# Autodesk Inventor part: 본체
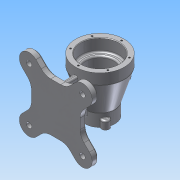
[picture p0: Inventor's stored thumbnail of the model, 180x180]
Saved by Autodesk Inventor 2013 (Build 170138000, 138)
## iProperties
Created: 2018-03
Part Number: 본체
Material: 알루미늄 6061
Document SubType Name: Modeling
Designer: Administrator
Density: 2.71 g/cm^3
Mass: 1014.04 g
Surface Area: 856.065 cm^2
Volume: 374.186 cm^3
Author: Administrator
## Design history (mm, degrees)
sketch "스케치1"
  geometry: L1 (45, 50)-(35, 50); L2 (35, 50)-(35, 27); L3 (35, 27)-(26, 27); L4 (26, 27)-(26, -20); L5 (26, -20)-(20, -20); L6 (20, -20)-(20, -50); L7 (20, -50)-(27.5, -50); L8 (27.5, -50)-(27.5, -27); L9 (27.5, -27)-(45, 30); L10 (45, 30)-(45, 50); L11 (0, 0)-(0, 61.227)
  constraints: 22 end point, 7 parallel, 1 horizontal, 1 perpendicular, 1 vertical
  dimensions: "d14" = 50 distance from line of L11.start L1; "d15" = 20 distance of L9.end L1.start; "d16" = 77 distance from line of L8.end L1; "d17" = 100 distance between parallel lines of L7 L1; "d18" = 23 distance of L1.end L2.end; "d19" = 47 distance of L3.end L4.end; "d20" = 40 diameter of L6 L11; "d21" = 55 diameter of L8 L11; "d22" = 90 diameter of L10 L11; "d23" = 70 diameter of L2 L11; "d24" = 52 diameter of L4 L11
revolve "회전1" sketch "스케치1" stored, may be unused: angle "d25" = 90 deg
node "작업 평면1"
sketch "스케치3"
  geometry: L1 (45, 45)-(-45, 45); L2 (-45, 45)-(-45, -45); L3 (-45, -45)-(45, -45); L4 (45, -45)-(45, 45); L5 (0, 0)-(65.909, 65.909); L6 (0, 0)-(114.42, 0); L7 (36.77, 62.225)-(19.544, 45); L8 (62.225, 36.77)-(45, 19.544); L9 (0, 0)-(73.646, -73.646); L10 (0, 0)-(-84.879, -84.879); L11 (0, 0)-(-79.002, 79.002); L12 (-36.77, 62.225)-(-19.544, 45); L13 (45, -19.544)-(62.225, -36.77); L14 (19.544, -45)-(36.77, -62.225); L15 (-19.544, -45)-(-36.77, -62.225); L16 (-45, -19.544)-(-62.225, -36.77); L17 (-45, 19.544)-(-62.225, 36.77); A1 r 70 centre (0, 0) between (49.497, 49.497) and (49.497, -49.497); A2 r 18 centre (49.497, 49.497) between (62.225, 36.77) and (36.77, 62.225); A3 r 18 centre (-49.497, 49.497) between (-36.77, 62.225) and (-62.225, 36.77); A4 r 18 centre (-49.497, -49.497) between (-62.225, -36.77) and (-36.77, -62.225); A5 r 18 centre (49.497, -49.497) between (36.77, -62.225) and (62.225, -36.77); 3 further points
  constraints: 34 end point, 12 point on circle, 12 point on line, 10 parallel, 8 tangent, 5 centre point, 3 perpendicular, 2 midpoint, 1 coincident, 1 horizontal, 1 horizontal alignment, 1 vertical alignment
  dimensions: "d46" = 90 distance of L1.start L1.end; "d48" = 90 distance of L3.end L1.start; "d49" = 140 diameter of A1; "d50" = 45 deg angle of L6 L5; "d52" = 18 radius of A2; "d53" = 90 deg angle of L10 L9; "d54" = 90 deg angle of L10 L11; "d58" = 18 radius of A5; "d59" = 18 radius of A3; "d60" = 18 radius of A4
extrude "돌출3" join sketch "스케치3" distance "d61" = 12; taper "d62" = 0 deg
sketch "스케치4"
  geometry: L1 (-24, -4)-(24, -4); L2 (24, -4)-(24, 4); L3 (24, 4)-(-24, 4); L4 (-24, 4)-(-24, -4); L5 (-4, -37)-(4, -37); L6 (4, -37)-(4, 37); L7 (4, 37)-(-4, 37); L8 (-4, 37)-(-4, -37); 4 further points
  constraints: 16 end point, 4 parallel, 3 midpoint, 2 horizontal, 2 perpendicular, 2 vertical alignment, 1 horizontal alignment
  dimensions: "d64" = 37 distance from line of point (0, 0) L5; "d65" = 37 distance from line of point (0, 0) L7; "d67" = 48 distance between parallel lines of L2 L4; "d68" = 8 distance between parallel lines of L6 L8; "d69" = 8 distance between parallel lines of L3 L1
extrude "돌출4" join sketch "스케치4" stored distance "d70" = 12; taper "d71" = 0 deg
feature "면 기울기1" dims angle "d72" = 5 deg
node "작업 평면2"
sketch "스케치5"
  geometry: L1 (-12.5, 12.5)-(12.5, 12.5); L2 (12.5, 12.5)-(12.5, -12.5); L3 (12.5, -12.5)-(-12.5, -12.5); L4 (-12.5, -12.5)-(-12.5, 12.5); L5 (-7.5, 7.5)-(7.5, 7.5); L6 (7.5, 7.5)-(7.5, -7.5); L7 (7.5, -7.5)-(-7.5, -7.5); L8 (-7.5, -7.5)-(-7.5, 7.5); 5 further points
  constraints: 16 end point, 4 midpoint, 4 parallel, 2 horizontal, 2 horizontal alignment, 2 perpendicular, 2 vertical alignment
  dimensions: "d74" = 25 distance of L3.end L1.start; "d76" = 25 distance of L1.start L1.end; "d77" = 15 distance of L5.end L6.end; "d78" = 15 distance of L6.end L7.end
extrude "돌출5" join sketch "스케치5" stored distance "d79" = 0; taper "d80" = 0 deg
extrude "돌출6" cut sketch "스케치5" stored distance "d81" = 12; taper "d82" = 0 deg
sketch "스케치6"
  geometry: L1 (0, 0)-(0, 27.5); L2 (0, 0)-(23.816, -13.75); L3 (0, 0)-(-23.816, -13.75); C1 r 7 at (0, 27.5); C2 r 7 at (-23.816, -13.75); C3 r 7 at (23.816, -13.75); A1 r 27.5 centre (0, 0) between (23.816, -13.75) and (-23.816, -13.75) reference
  constraints: 6 end point, 3 centre point, 3 coincident, 3 point on circle, 2 equal radius, 1 vertical
  dimensions: "d83" = 120 deg angle of L1 L3; "d84" = 120 deg angle of L1 L2; "d85" = 14 diameter of C1
extrude "돌출7" join sketch "스케치6" distance "d87" = 15; taper "d88" = 0 deg
hole "구멍1" diameter "d91" = 10; stored, may be unused: countersink angle "d95" = 90 deg, drill point angle "d97" = 118 deg; dims "d89" = 10, "d90" = 10, "d92" = 6, "d93" = 4, "d94" = 2, "d96" = 8
hole "구멍2" diameter "d100" = 10; stored, may be unused: countersink angle "d104" = 90 deg, drill point angle "d106" = 118 deg; dims "d98" = 10, "d99" = 10, "d101" = 6, "d102" = 4, "d103" = 2, "d105" = 8
hole "구멍3" diameter "d109" = 10; stored, may be unused: countersink angle "d113" = 90 deg, drill point angle "d115" = 118 deg; dims "d107" = 10, "d108" = 10, "d110" = 6, "d111" = 4, "d112" = 2, "d114" = 8
hole "구멍4" diameter "d118" = 10; stored, may be unused: countersink angle "d122" = 90 deg, drill point angle "d124" = 118 deg; dims "d116" = 10, "d117" = 10, "d119" = 6, "d120" = 4, "d121" = 2, "d123" = 8
sketch "스케치7"
  geometry: C1 r 45 at (0, 0) reference; 1 further point
  constraints: 1 vertical alignment
  dimensions: "d125" = 40 distance of C1.centre point (0, 40)
hole "구멍5" sketch "스케치7" at (0, 40) diameter "d126" = 3.242; stored, may be unused: countersink angle "d130" = 90 deg, drill point angle "d132" = 118 deg; dims "d127" = 9, "d128" = 4, "d129" = 2, "d131" = 11
hole "구멍6" diameter "d138" = 3.242; stored, may be unused: countersink angle "d142" = 90 deg, drill point angle "d144" = 118 deg; dims "d136" = 10, "d137" = 10, "d139" = 9, "d140" = 4, "d141" = 2, "d143" = 11
fillet "모깎기1" dims "d148" = 3
fillet "모깎기2" dims "d149" = 3
fillet "모깎기3" dims "d150" = 8, "d151" = 3
fillet "모깎기4" dims "d152" = 1
fillet "모깎기5" dims "d153" = 3
fillet "모깎기6" dims "d154" = 1
fillet "모깎기8" dims "d156" = 25
fillet "모깎기7" dims "d155" = 3
fillet "모깎기9" dims "d157" = 3
chamfer "모따기1" distance "d159" = 1; stored, may be unused: second distance "d160" = 2, angle "d161" = 45 deg
sketch "스케치9"
  geometry: 2 further points
  constraints: 1 horizontal alignment, 1 other
  dimensions: "d162" = 35 distance of point (0, 0) point (35, 0)
feature "엠보싱1" sketch "스케치9" dims "d163" = 0.5, "d164" = 0
chamfer "모따기2" distance "d165" = 3; stored, may be unused: second distance "d166" = 2, angle "d167" = 45 deg
chamfer "모따기3" distance "d168" = 1; stored, may be unused: second distance "d169" = 2, angle "d170" = 45 deg
node "솔리드1"
pattern_circular "원형 패턴1" dims angle "d134" = 360 deg
pattern_circular "원형 패턴2" dims angle "d146" = 360 deg
other parameters: "d26" = -82, "d51" = 36, "d55" = 36, "d56" = 36, "d57" = 36, "d73" = 45
